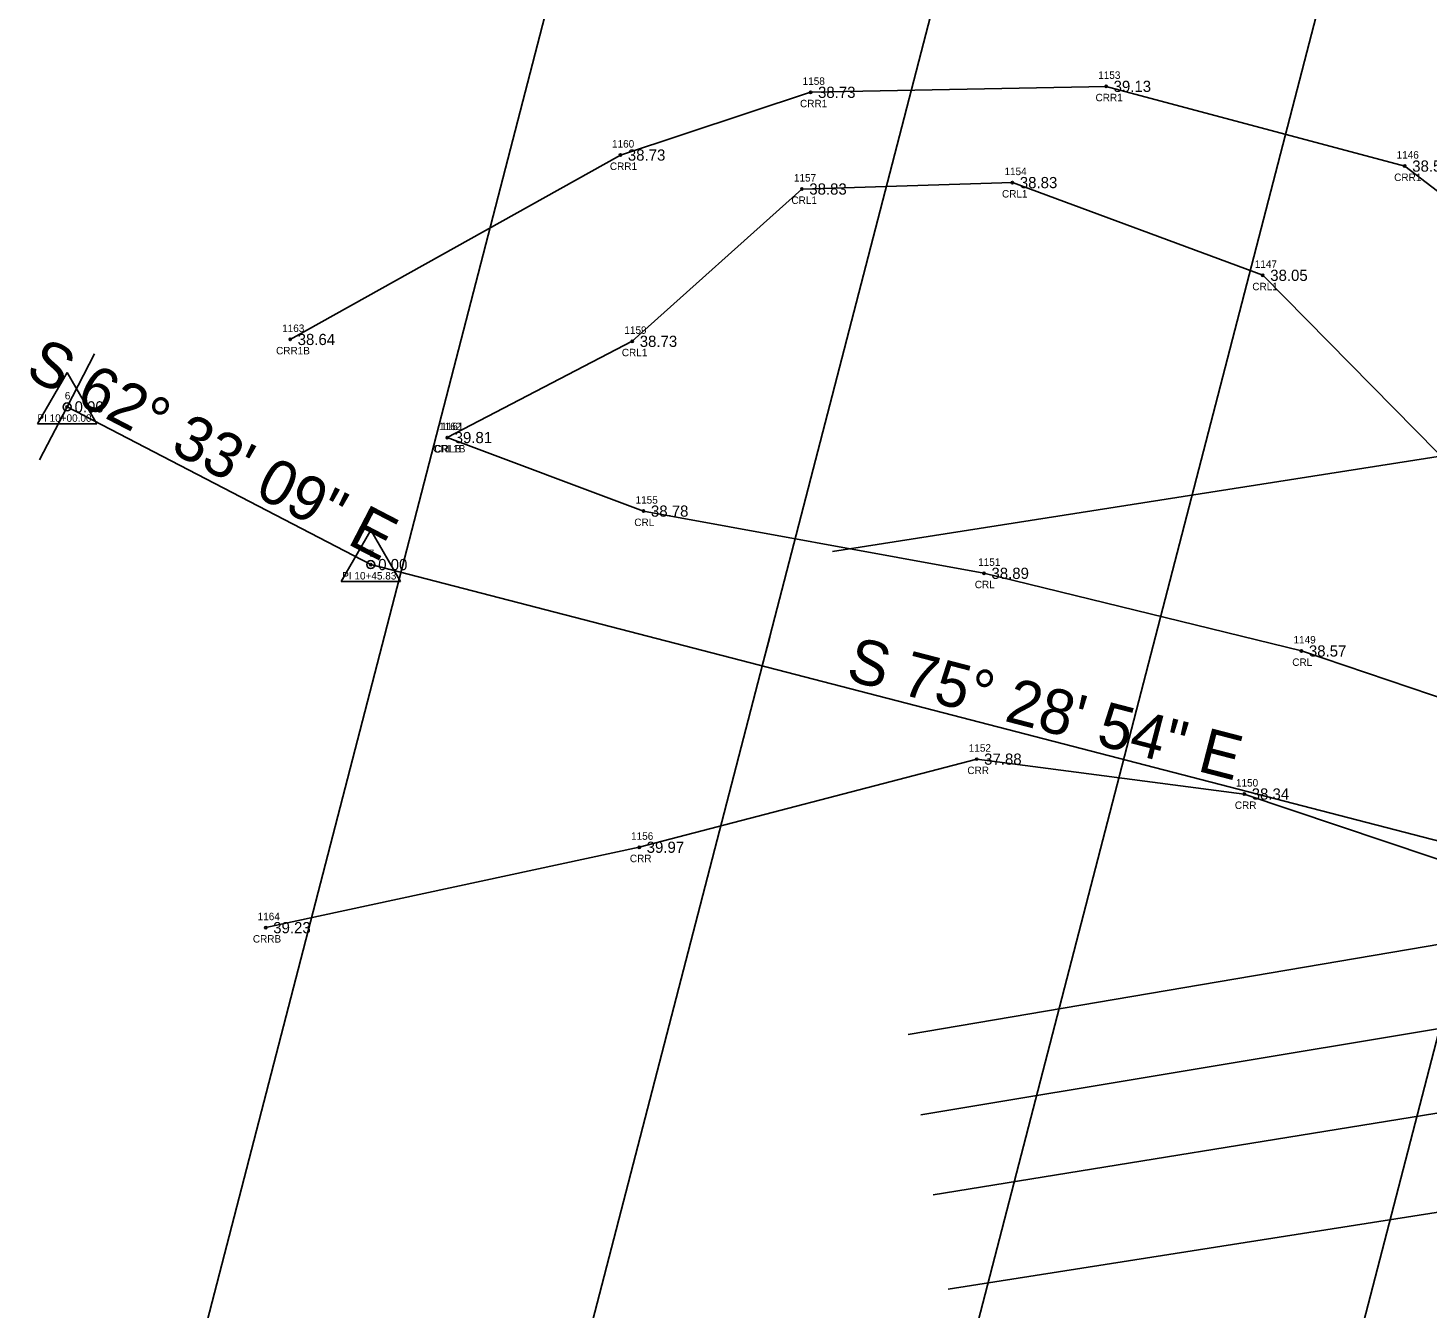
# Model space of a CAD drawing. Extents: x 2619568 to 2620316, y 784340 to 785138.
# Drawn here: x 2619568.4 to 2619755.9, y 784773.8 to 784945.3 of the extents above; entities that cross this region are included whole.
import ezdxf

# ---------------------------------------------------------------- set-up
doc = ezdxf.new("R2010")
doc.units = 0
for name, color, linetype in [('RD_EX_H2O', 7, 'Continuous'), ('RD_EX_H2O_txCode', 7, 'Continuous'), ('RD_EX_TX_H2O_ELEV', 7, 'Continuous'), ('RD_HC_Cl', 7, 'Continuous'), ('RD_HC_Data', 7, 'Continuous'), ('RD_HC_Data_Tic', 7, 'Continuous'), ('RD_HC_Survey_ELEV', 7, 'Continuous'), ('RD_HC_txCode', 7, 'Continuous'), ('RD_PD_PatLn1', 7, 'Continuous'), ('RD_PD_PatLn2', 7, 'Continuous'), ('RD_PD_PatLn3', 7, 'Continuous'), ('RD_SMD_Locator', 7, 'Continuous')]:
    doc.layers.add(name, color=color, linetype=linetype)

msp = doc.modelspace()

# ---------------------------------------------------------------- linework, layer by layer
at = {"layer": 'RD_EX_H2O'}
for points in [[(2619772.64, 784911.68), (2619752.83, 784926.84), (2619712.83, 784937.52), (2619673.24, 784936.72), (2619647.77, 784928.32), (2619603.54, 784903.62)], [(2619773.83, 784850.15), (2619780.57, 784864.79), (2619733.81, 784912.21), (2619700.27, 784924.63), (2619672.07, 784923.77), (2619649.36, 784903.37), (2619624.57, 784890.48)], [(2619773.83, 784850.15), (2619738.99, 784861.9), (2619696.47, 784872.3), (2619650.86, 784880.63), (2619624.57, 784890.48)], [(2619816.05, 784799.8), (2619788.01, 784803.33), (2619762.86, 784832.16), (2619731.33, 784842.74), (2619695.49, 784847.41), (2619650.29, 784835.61), (2619600.27, 784824.84)]]:
    msp.add_lwpolyline(points, dxfattribs=at)
at = {"layer": 'RD_HC_Cl'}
for p, q in [((2619573.66, 784894.59), (2619614.33, 784873.47)), ((2619614.33, 784873.47), (2619798, 784825.91))]:
    msp.add_line(p, q, dxfattribs=at)
at = {"layer": 'RD_HC_Data'}
for p, q in [((2619569.69, 784892.3), (2619573.66, 784899.18)), ((2619573.66, 784899.18), (2619577.63, 784892.3)), ((2619569.69, 784892.3), (2619577.63, 784892.3)), ((2619610.36, 784871.18), (2619614.33, 784878.06)), ((2619614.33, 784878.06), (2619618.3, 784871.18)), ((2619610.36, 784871.18), (2619618.3, 784871.18))]:
    msp.add_line(p, q, dxfattribs=at)
for centre in [(2619573.66, 784894.59), (2619614.33, 784873.47)]:
    msp.add_circle(centre, 0.529, dxfattribs=at)
at = {"layer": 'RD_HC_Data_Tic'}
for p, q in [((2619573.66, 784894.59), (2619577.35, 784901.69)), ((2619573.66, 784894.59), (2619569.97, 784887.49)), ((2619666.77, 784859.89), (2619667.77, 784863.76))]:
    msp.add_line(p, q, dxfattribs=at)
at = {"layer": 'RD_PD_PatLn1'}
for p, q in [((2619972.54, 784921.71), (2619676.16, 784875.24)), ((2619988.03, 784822.91), (2619691.65, 784776.44))]:
    msp.add_line(p, q, dxfattribs=at)
at = {"layer": 'RD_PD_PatLn2'}
for p, q in [((2619655.97, 785017.63), (2619580.76, 784727.21)), ((2619704.37, 785005.1), (2619629.17, 784714.68)), ((2619752.78, 784992.56), (2619677.57, 784702.14)), ((2619801.18, 784980.03), (2619725.97, 784689.61))]:
    msp.add_line(p, q, dxfattribs=at)
at = {"layer": 'RD_PD_PatLn3'}
for p, q in [((2619686.31, 784810.54), (2619982.1, 784860.72)), ((2619687.99, 784799.79), (2619983.95, 784848.95)), ((2619689.68, 784789.04), (2619985.79, 784837.19))]:
    msp.add_line(p, q, dxfattribs=at)
at = {"layer": 'RD_SMD_Locator'}
for centre in [(2619673.24, 784936.72), (2619712.83, 784937.52), (2619647.77, 784928.32), (2619752.83, 784926.84), (2619672.07, 784923.77), (2619700.27, 784924.63), (2619733.81, 784912.21), (2619603.54, 784903.62), (2619649.36, 784903.37), (2619573.66, 784894.59), (2619624.57, 784890.48), (2619624.57, 784890.48), (2619650.86, 784880.63), (2619614.33, 784873.47), (2619696.47, 784872.3), (2619738.99, 784861.9), (2619695.49, 784847.41), (2619731.33, 784842.74), (2619650.29, 784835.61), (2619600.27, 784824.84)]:
    msp.add_circle(centre, 0.15, dxfattribs=at)

# ---------------------------------------------------------------- texts
at = {"layer": 'RD_EX_H2O_txCode'}
for s, p in [('1158', (2619672.18, 784937.72)), ('1153', (2619711.77, 784938.52)), ('CRR1', (2619671.83, 784934.72)), ('CRR1', (2619711.41, 784935.52)), ('1160', (2619646.65, 784929.32)), ('1146', (2619751.74, 784927.84)), ('CRR1', (2619646.36, 784926.32)), ('1157', (2619671.01, 784924.77)), ('1154', (2619699.21, 784925.63)), ('CRR1', (2619751.41, 784924.84)), ('CRL1', (2619698.88, 784922.63)), ('CRL1', (2619670.68, 784921.77)), ('1147', (2619732.74, 784913.21)), ('CRL1', (2619732.41, 784910.21)), ('1163', (2619602.46, 784904.62)), ('1159', (2619648.3, 784904.37)), ('CRR1B', (2619601.65, 784901.62)), ('CRL1', (2619647.96, 784901.37)), ('1162', (2619623.48, 784891.48)), ('1161', (2619623.76, 784891.48)), ('CRL1B', (2619622.7, 784888.48)), ('CRLB', (2619622.86, 784888.48)), ('1155', (2619649.8, 784881.63)), ('CRL', (2619649.63, 784878.63)), ('1151', (2619695.69, 784873.3)), ('CRL', (2619695.24, 784870.3)), ('1149', (2619737.93, 784862.9)), ('CRL', (2619737.76, 784859.9)), ('1152', (2619694.43, 784848.41)), ('CRR', (2619694.24, 784845.41)), ('1150', (2619730.22, 784843.74)), ('CRR', (2619730.07, 784840.74)), ('1156', (2619649.2, 784836.61)), ('CRR', (2619649.04, 784833.61)), ('1164', (2619599.18, 784825.84)), ('CRRB', (2619598.54, 784822.84))]:
    msp.add_text(s, height=1, dxfattribs=at).set_placement(p)
at = {"layer": 'RD_EX_TX_H2O_ELEV'}
for s, p in [('38.73', (2619674.24, 784935.97)), ('39.13', (2619713.83, 784936.77)), ('38.73', (2619648.77, 784927.57)), ('38.55', (2619753.83, 784926.09)), ('38.83', (2619673.07, 784923.02)), ('38.83', (2619701.27, 784923.88)), ('38.05', (2619734.81, 784911.46)), ('38.64', (2619604.54, 784902.87)), ('38.73', (2619650.36, 784902.62)), ('39.81', (2619625.57, 784889.73)), ('39.81', (2619625.57, 784889.73)), ('38.78', (2619651.86, 784879.88)), ('38.89', (2619697.47, 784871.55)), ('38.57', (2619739.99, 784861.15)), ('37.88', (2619696.49, 784846.66)), ('38.34', (2619732.33, 784841.99)), ('39.97', (2619651.29, 784834.86)), ('39.23', (2619601.27, 784824.09))]:
    msp.add_text(s, height=1.5, dxfattribs=at).set_placement(p)
at = {"layer": 'RD_HC_Data'}
for s, rotation, p in [('S 62%%d 33\' 09" E', 332.5524, (2619567.85, 784898.74)), ('S 75%%d 28\' 54" E', 345.4816, (2619677.81, 784858.06))]:
    msp.add_text(s, height=6, rotation=rotation, dxfattribs=at).set_placement(p)
at = {"layer": 'RD_HC_Survey_ELEV'}
for p in [(2619574.66, 784893.84), (2619615.33, 784872.72)]:
    msp.add_text('0.00', height=1.5, dxfattribs=at).set_placement(p)
at = {"layer": 'RD_HC_txCode'}
for s, p in [('6', (2619573.35, 784895.59)), ('PI 10+00.00', (2619569.68, 784892.59)), ('7', (2619614.05, 784874.47)), ('PI 10+45.83', (2619610.51, 784871.47))]:
    msp.add_text(s, height=1, dxfattribs=at).set_placement(p)

doc.saveas('drawing.dxf')
